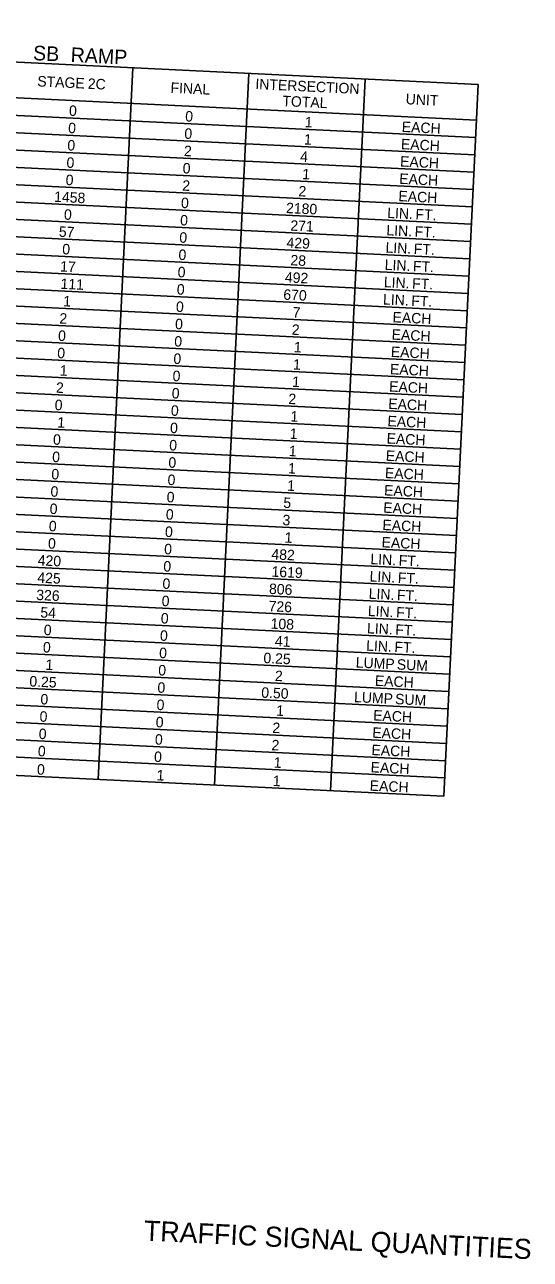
# Model space of a CAD drawing. Extents: x 669100 to 670801, y 741155 to 743955.
# Drawn here: x 669585.2 to 669706, y 743337.1 to 743632.3 of the extents above; entities that cross this region are included whole.
import ezdxf

# ---------------------------------------------------------------- set-up
doc = ezdxf.new("R2010")
doc.units = 0
doc.layers.add('R_Dimension', color=7, linetype='Continuous')
doc.layers.add('R_Horz Alg Annot', color=7, linetype='Continuous')

msp = doc.modelspace()

# ---------------------------------------------------------------- linework, layer by layer
at = {"layer": 'R_Dimension'}
for p, q in [((669398.51, 743632.34), (669693.59, 743618.01)), ((669398.1, 743623.82), (669693.18, 743609.49)), ((669602.79, 743451.84), (669611.06, 743622.02)), ((669397.9, 743619.68), (669692.97, 743605.35)), ((669630.55, 743450.49), (669638.81, 743620.67)), ((669658.3, 743449.15), (669666.56, 743619.33)), ((669685.33, 743447.83), (669693.59, 743618.01)), ((669397.7, 743615.54), (669692.77, 743601.21)), ((669397.49, 743611.4), (669692.57, 743597.08)), ((669397.29, 743607.27), (669692.37, 743592.94)), ((669397.09, 743603.13), (669692.17, 743588.8)), ((669396.89, 743598.99), (669691.97, 743584.66)), ((669396.69, 743594.85), (669691.77, 743580.52)), ((669396.49, 743590.71), (669691.57, 743576.38)), ((669396.29, 743586.57), (669691.37, 743572.24)), ((669396.09, 743582.43), (669691.17, 743568.1)), ((669395.89, 743578.29), (669690.96, 743563.96)), ((669395.69, 743574.15), (669690.76, 743559.83)), ((669395.49, 743570.02), (669690.56, 743555.69)), ((669395.28, 743565.88), (669690.36, 743551.55)), ((669395.08, 743561.74), (669690.16, 743547.41)), ((669394.88, 743557.6), (669689.96, 743543.27)), ((669394.68, 743553.46), (669689.76, 743539.13)), ((669394.48, 743549.32), (669689.56, 743534.99)), ((669394.28, 743545.18), (669689.36, 743530.85)), ((669394.08, 743541.04), (669689.16, 743526.71)), ((669393.88, 743536.9), (669688.95, 743522.58)), ((669393.68, 743532.77), (669688.75, 743518.44)), ((669393.48, 743528.63), (669688.55, 743514.3)), ((669393.27, 743524.49), (669688.35, 743510.16)), ((669393.07, 743520.35), (669688.15, 743506.02)), ((669392.87, 743516.21), (669687.95, 743501.88)), ((669392.67, 743512.07), (669687.75, 743497.74)), ((669392.47, 743507.93), (669687.55, 743493.6)), ((669392.27, 743503.79), (669687.35, 743489.46)), ((669392.07, 743499.65), (669687.15, 743485.33)), ((669391.87, 743495.52), (669686.94, 743481.19)), ((669391.67, 743491.38), (669686.74, 743477.05)), ((669391.47, 743487.24), (669686.54, 743472.91)), ((669391.26, 743483.1), (669686.34, 743468.77)), ((669391.06, 743478.96), (669686.14, 743464.63)), ((669390.86, 743474.82), (669685.94, 743460.49)), ((669390.66, 743470.68), (669685.74, 743456.35)), ((669390.46, 743466.54), (669685.54, 743452.22)), ((669390.25, 743462.16), (669685.33, 743447.83))]:
    msp.add_line(p, q, dxfattribs=at)

# ---------------------------------------------------------------- texts
for s, height, p in [(' SB', 3.5, (669585.87, 743623.94)), (' RAMP', 3.5, (669594.85, 743623.51)), ('STAGE', 2.5, (669588.2, 743617.61)), (' 2C', 2.5, (669599.33, 743617.07)), ('INTERSECTION', 2.5, (669640.29, 743616.96)), ('FINAL', 2.5, (669620.02, 743616.06)), ('UNIT', 2.5, (669676.2, 743613.34)), ('0', 2.5, (669595.77, 743610.57)), ('TOTAL', 2.5, (669646.74, 743612.89)), ('0', 2.5, (669623.53, 743609.23)), ('1', 2.5, (669652.1, 743607.84)), ('0', 2.5, (669595.57, 743606.44)), ('0', 2.5, (669623.32, 743605.09)), ('EACH', 2.5, (669675.26, 743606.71)), ('0', 2.5, (669595.37, 743602.3)), ('1', 2.5, (669651.9, 743603.7)), ('EACH', 2.5, (669675.06, 743602.58)), ('2', 2.5, (669623.23, 743600.94)), ('4', 2.5, (669650.99, 743599.6)), ('EACH', 2.5, (669674.86, 743598.44)), ('0', 2.5, (669595.17, 743598.16)), ('0', 2.5, (669622.92, 743596.81)), ('0', 2.5, (669594.97, 743594.02)), ('2', 2.5, (669622.83, 743592.67)), ('1', 2.5, (669651.49, 743595.42)), ('EACH', 2.5, (669674.66, 743594.3)), ('1458', 2.5, (669592.22, 743590)), ('2', 2.5, (669650.58, 743591.32)), ('EACH', 2.5, (669674.46, 743590.16)), ('0', 2.5, (669622.52, 743588.53)), ('2180', 2.5, (669647.62, 743587.31)), ('0', 2.5, (669594.57, 743585.74)), ('0', 2.5, (669622.32, 743584.39)), ('LIN.', 2.5, (669671.79, 743586.14)), (' FT.', 2.5, (669677.61, 743585.86)), ('57', 2.5, (669593.35, 743581.65)), ('271', 2.5, (669648.65, 743583.11)), ('LIN.', 2.5, (669671.59, 743582)), (' FT.', 2.5, (669677.41, 743581.72)), ('0', 2.5, (669622.12, 743580.25)), ('429', 2.5, (669647.73, 743579.01)), ('LIN.', 2.5, (669671.38, 743577.86)), ('0', 2.5, (669594.16, 743577.46)), ('0', 2.5, (669621.92, 743576.12)), ('28', 2.5, (669648.66, 743574.82)), (' FT.', 2.5, (669677.2, 743577.58)), ('17', 2.5, (669593.66, 743573.34)), ('0', 2.5, (669621.72, 743571.98)), ('LIN.', 2.5, (669671.18, 743573.72)), (' FT.', 2.5, (669677, 743573.44)), ('111', 2.5, (669593.75, 743569.19)), ('492', 2.5, (669647.34, 743570.73)), ('LIN.', 2.5, (669670.98, 743569.58)), (' FT.', 2.5, (669676.8, 743569.3)), ('0', 2.5, (669621.52, 743567.84)), ('670', 2.5, (669646.97, 743566.6)), ('1', 2.5, (669594.38, 743565.01)), ('0', 2.5, (669621.32, 743563.7)), ('LIN.', 2.5, (669670.78, 743565.45)), (' FT.', 2.5, (669676.6, 743565.16)), ('2', 2.5, (669593.47, 743560.9)), ('7', 2.5, (669649.18, 743562.35)), ('EACH', 2.5, (669673.05, 743561.19)), ('0', 2.5, (669621.11, 743559.56)), ('2', 2.5, (669648.98, 743558.21)), ('EACH', 2.5, (669672.85, 743557.05)), ('0', 2.5, (669593.16, 743556.77)), ('0', 2.5, (669620.91, 743555.42)), ('0', 2.5, (669592.96, 743552.63)), ('0', 2.5, (669620.71, 743551.28)), ('1', 2.5, (669649.48, 743554.03)), ('EACH', 2.5, (669672.65, 743552.91)), ('1', 2.5, (669593.57, 743548.45)), ('1', 2.5, (669649.28, 743549.89)), ('EACH', 2.5, (669672.45, 743548.77)), ('0', 2.5, (669620.51, 743547.14)), ('1', 2.5, (669649.08, 743545.76)), ('2', 2.5, (669592.66, 743544.35)), ('0', 2.5, (669620.31, 743543)), ('EACH', 2.5, (669672.24, 743544.63)), ('0', 2.5, (669592.35, 743540.21)), ('2', 2.5, (669648.17, 743541.65)), ('EACH', 2.5, (669672.04, 743540.49)), ('0', 2.5, (669620.11, 743538.87)), ('1', 2.5, (669648.68, 743537.48)), ('1', 2.5, (669592.97, 743536.03)), ('0', 2.5, (669619.91, 743534.73)), ('EACH', 2.5, (669671.84, 743536.35)), ('0', 2.5, (669591.95, 743531.94)), ('0', 2.5, (669619.71, 743530.59)), ('1', 2.5, (669648.48, 743533.34)), ('EACH', 2.5, (669671.64, 743532.21)), ('0', 2.5, (669591.75, 743527.8)), ('1', 2.5, (669648.28, 743529.2)), ('EACH', 2.5, (669671.44, 743528.08)), ('0', 2.5, (669619.51, 743526.45)), ('1', 2.5, (669648.08, 743525.06)), ('0', 2.5, (669591.55, 743523.66)), ('0', 2.5, (669619.31, 743522.31)), ('EACH', 2.5, (669671.24, 743523.94)), ('0', 2.5, (669591.35, 743519.52)), ('1', 2.5, (669647.88, 743520.92)), ('EACH', 2.5, (669671.04, 743519.8)), ('0', 2.5, (669619.1, 743518.17)), ('5', 2.5, (669646.97, 743516.82)), ('0', 2.5, (669591.15, 743515.38)), ('0', 2.5, (669618.9, 743514.03)), ('EACH', 2.5, (669670.84, 743515.66)), ('0', 2.5, (669590.95, 743511.24)), ('0', 2.5, (669618.7, 743509.89)), ('3', 2.5, (669646.77, 743512.68)), ('EACH', 2.5, (669670.64, 743511.52)), ('0', 2.5, (669590.75, 743507.1)), ('1', 2.5, (669647.27, 743508.51)), ('EACH', 2.5, (669670.44, 743507.38)), ('0', 2.5, (669618.5, 743505.75)), ('482', 2.5, (669644.12, 743504.51)), ('420', 2.5, (669588.3, 743503.07)), ('0', 2.5, (669618.3, 743501.62)), ('LIN.', 2.5, (669667.77, 743503.36)), (' FT.', 2.5, (669673.59, 743503.08)), ('425', 2.5, (669588.21, 743498.93)), ('1619', 2.5, (669644.15, 743500.36)), ('LIN.', 2.5, (669667.57, 743499.22)), (' FT.', 2.5, (669673.39, 743498.94)), ('0', 2.5, (669618.1, 743497.48)), ('806', 2.5, (669643.55, 743496.24)), ('LIN.', 2.5, (669667.36, 743495.08)), ('326', 2.5, (669587.94, 743494.79)), ('0', 2.5, (669617.9, 743493.34)), ('726', 2.5, (669643.45, 743492.1)), (' FT.', 2.5, (669673.18, 743494.8)), ('54', 2.5, (669588.93, 743490.6)), ('0', 2.5, (669617.7, 743489.2)), ('LIN.', 2.5, (669667.16, 743490.95)), (' FT.', 2.5, (669672.98, 743490.66)), ('0', 2.5, (669589.74, 743486.41)), ('108', 2.5, (669643.93, 743487.93)), ('LIN.', 2.5, (669666.96, 743486.81)), (' FT.', 2.5, (669672.78, 743486.52)), ('0', 2.5, (669617.5, 743485.06)), ('41', 2.5, (669644.95, 743483.73)), ('0', 2.5, (669589.54, 743482.27)), ('0', 2.5, (669617.3, 743480.92)), ('LIN.', 2.5, (669666.76, 743482.67)), (' FT.', 2.5, (669672.58, 743482.39)), ('1', 2.5, (669590.16, 743478.09)), ('0.25', 2.5, (669642.21, 743479.71)), ('LUMP', 2.5, (669664.27, 743478.64)), (' SUM', 2.5, (669673.14, 743478.21)), ('0', 2.5, (669617.09, 743476.78)), ('2', 2.5, (669644.96, 743475.43)), ('0.25', 2.5, (669586.3, 743474.13)), ('0', 2.5, (669616.89, 743472.64)), ('0.50', 2.5, (669641.7, 743471.44)), ('EACH', 2.5, (669668.83, 743474.27)), ('0', 2.5, (669588.94, 743469.85)), ('0', 2.5, (669616.69, 743468.5)), ('LUMP', 2.5, (669663.87, 743470.36)), (' SUM', 2.5, (669672.74, 743469.93)), ('0', 2.5, (669588.74, 743465.71)), ('1', 2.5, (669645.26, 743467.12)), ('EACH', 2.5, (669668.43, 743465.99)), ('0', 2.5, (669616.49, 743464.37)), ('2', 2.5, (669644.35, 743463.01)), ('0', 2.5, (669588.54, 743461.57)), ('0', 2.5, (669616.29, 743460.23)), ('EACH', 2.5, (669668.22, 743461.85)), ('0', 2.5, (669588.33, 743457.44)), ('2', 2.5, (669644.15, 743458.87)), ('EACH', 2.5, (669668.02, 743457.71)), ('0', 2.5, (669616.09, 743456.09)), ('1', 2.5, (669644.66, 743454.7)), ('0', 2.5, (669588.12, 743453.05)), ('1', 2.5, (669616.69, 743451.67)), ('EACH', 2.5, (669667.82, 743453.58)), ('1', 2.5, (669644.45, 743450.32)), ('EACH', 2.5, (669667.61, 743449.19))]:
    msp.add_text(s, height=height, rotation=357.2199, dxfattribs=at).set_placement(p)
at = {"layer": 'R_Horz Alg Annot'}
msp.add_text('TRAFFIC SIGNAL QUANTITIES', height=4.8, rotation=357.2199, dxfattribs=at).set_placement((669613.61, 743341.63))

doc.saveas('drawing.dxf')
